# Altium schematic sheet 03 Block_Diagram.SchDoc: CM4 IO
size 420 x 297 mm; Page Create Date: March  8, 1995; Page Number: 3; Page Size: A3; Comment: radxa_1010; Page Count: 19; RevCode: V1.10; Doc: 03 Block_Diagram; DsnPath: D:\WMS\黄工\[RC126]CM4_IO_V1.10\[RC126]_V1.10\CM4 IO_V1.10.DSN; SchematicName: CM4 IO V1.10; PageName: 03 Block_Diagram; PageSize: A3; TopSchematic: True
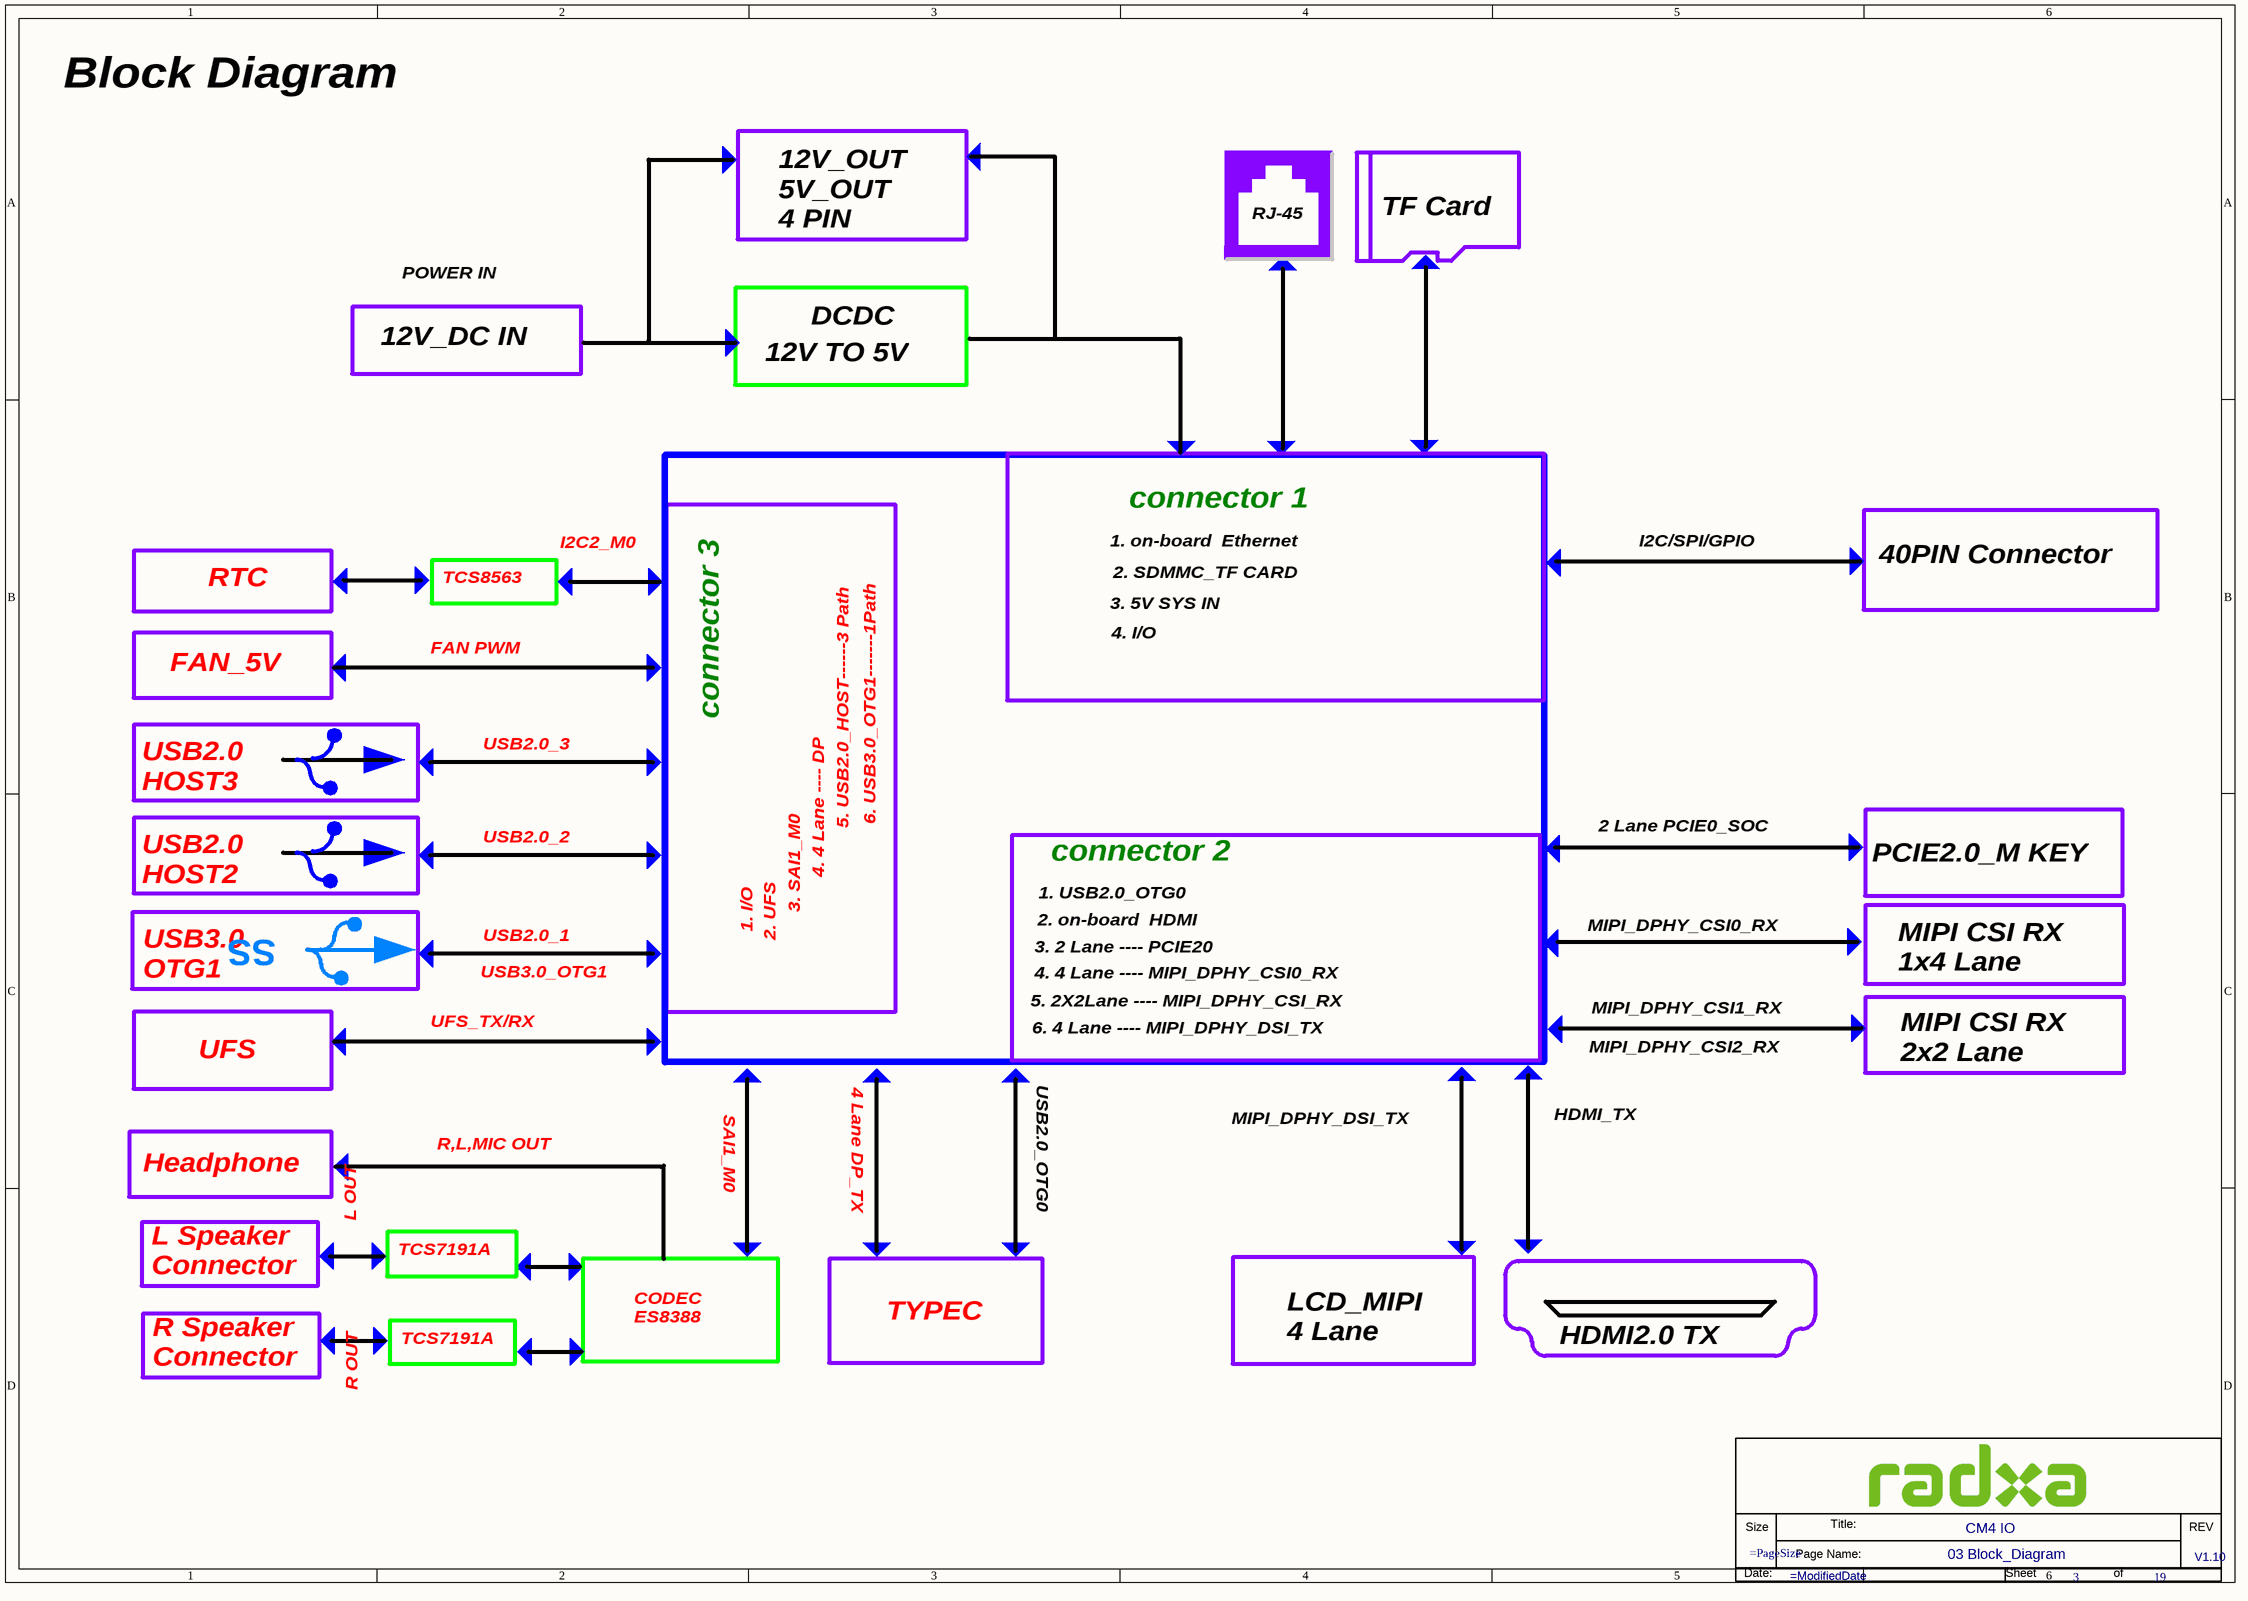
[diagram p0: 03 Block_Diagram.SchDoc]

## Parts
*  Doc: 03 Block_Diagram  RevCode: V1.10  Title: CM4 IO  Page Number: 3  Page Count: 19  (hidden comment: radxa_1010)  (graphical)

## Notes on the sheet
- Block Diagram
- 12V_OUT
  5V_OUT
  4 PIN
- RJ-45
- TF Card
- 12V_DC IN
- POWER IN
- DCDC
- 12V TO 5V
- connector 1
- RTC
- TCS8563
- I2C2_M0
- 1. on-board  Ethernet
- 2. SDMMC_TF CARD
- I2C/SPI/GPIO
- 40PIN Connector
- FAN PWM
- 3. 5V SYS IN
- 4. I/O
- USB2.0
  HOST3
- FAN_5V
- USB2.0_3
- connector 3
- USB2.0
  HOST2
- USB2.0_2
- 5. USB2.0_HOST------3 Path
- 6. USB3.0_OTG1-------1Path
- connector 2
- 2 Lane PCIE0_SOC
- PCIE2.0_M KEY
- USB3.0
  OTG1
- SS
- USB2.0_1
- 1. I/O
- 2. UFS
- 3. SAI1_M0
- 4. 4 Lane ---- DP
- 2. on-board  HDMI
- 1. USB2.0_OTG0
- MIPI_DPHY_CSI0_RX
- MIPI CSI RX
  1x4 Lane
- USB3.0_OTG1
- 4. 4 Lane ---- MIPI_DPHY_CSI0_RX
- 3. 2 Lane ---- PCIE20
- MIPI CSI RX
  2x2 Lane
- UFS
- UFS_TX/RX
- 5. 2X2Lane ---- MIPI_DPHY_CSI_RX
- 6. 4 Lane ---- MIPI_DPHY_DSI_TX
- MIPI_DPHY_CSI2_RX
- MIPI_DPHY_CSI1_RX
- SAI1_M0
- 4 Lane DP_TX
- USB2.0_OTG0
- MIPI_DPHY_DSI_TX
- HDMI_TX
- Headphone
- R,L,MIC OUT
- L Speaker
  Connector
- L OUT
- TCS7191A
- R Speaker
  Connector
- CODEC
  ES8388
- TYPEC
- LCD_MIPI
  4 Lane
- R OUT
- HDMI2.0 TX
